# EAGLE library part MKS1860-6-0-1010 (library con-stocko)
Serie MKS 1850 Lötstifte In-line, Raster 2.5 mm, Stiftwannen, stehend, mit Rastlasche Source: http://www.stocko.de/de/index.php?seite=ka_rfk2_mks1850.html&rubrik=Katalog+-+RFK+2 rfk_1850.pdf
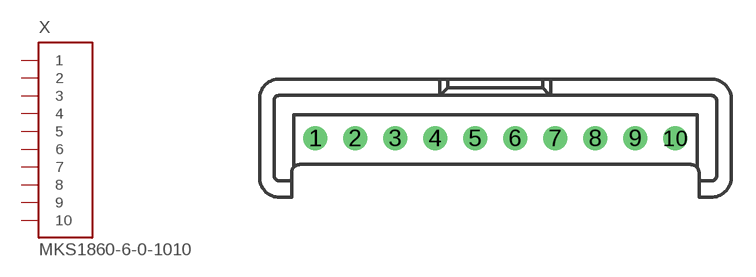
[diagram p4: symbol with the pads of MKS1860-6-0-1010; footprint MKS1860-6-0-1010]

Designator prefix X

## MKS1860-6-0-1010 (OC_FARNELL: unknown; OC_NEWARK: unknown)  [MKS1860-6-0-1010]
1  1  in
2  2  in
3  3  in
4  4  in
5  5  in
6  6  in
7  7  in
8  8  in
9  9  in
10  10  in

## Footprint MKS1860-6-0-1010 (pad centres in mm)
Serie MKS 1850 Lötstifte In-line, Raster 2.5 mm, Stiftwannen, stehend, mit Rastlasche Source: http://www.stocko.de/de/index.php?seite=ka_rfk2_mks1850.html&rubrik=Katalog+-+RFK+2 rfk_1850.pdf
drill 1 pad 1.422 round: 1 -11.25,0; 2 -8.75,0; 3 -6.25,0; 4 -3.75,0; 5 -1.25,0; 6 1.25,0; 7 3.75,0; 8 6.25,0; 9 8.75,0; 10 11.25,0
